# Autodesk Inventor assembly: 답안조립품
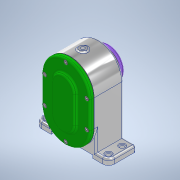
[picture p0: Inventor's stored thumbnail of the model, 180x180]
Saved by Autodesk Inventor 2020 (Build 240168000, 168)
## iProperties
Created: 2021-05
Part Number: 답안조립품
Document SubType Name: Assembly
Designer: Owner
Author: Owner
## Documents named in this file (19)
- C:\Users\Owner\Desktop\710507V1005\답안조립품.iam
- C:\Users\Owner\Desktop\710507V1005\본체.ipt
- C:\Users\Owner\Desktop\710507V1005\축 A.ipt
- C:\Users\Owner\Desktop\710507V1005\베어링 6001.ipt
- 베어링 6001.ipt
- C:\Users\Owner\Desktop\710507V1005\축 B.ipt
- C:\Users\Owner\Desktop\710507V1005\베어링 6002.ipt
- 베어링 6002.ipt
- C:\Users\Owner\Desktop\710507V1005\칼라.ipt
- C:\Users\Owner\Desktop\710507V1005\키 5 x 5 x 12.ipt
- C:\Users\Owner\Desktop\710507V1005\키 4 x 4 x 12.ipt
- C:\Users\Owner\Desktop\710507V1005\스퍼기어 A.ipt
- C:\Users\Owner\Desktop\710507V1005\스퍼기어 B.ipt
- C:\Users\Owner\Desktop\710507V1005\개스킷 A.ipt
- C:\Users\Owner\Desktop\710507V1005\개스킷 B.ipt
- C:\Users\Owner\Desktop\710507V1005\커버 A.ipt
- C:\Users\Owner\Desktop\710507V1005\커버 B.ipt
- C:\Users\Owner\Desktop\710507V1005\오일 실 12 22 7.ipt
- C:\Users\Owner\Desktop\710507V1005\볼트 M4.ipt
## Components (2 placed, 2 different names)
1. 개스킷 A:1
2. 개스킷 B:1
